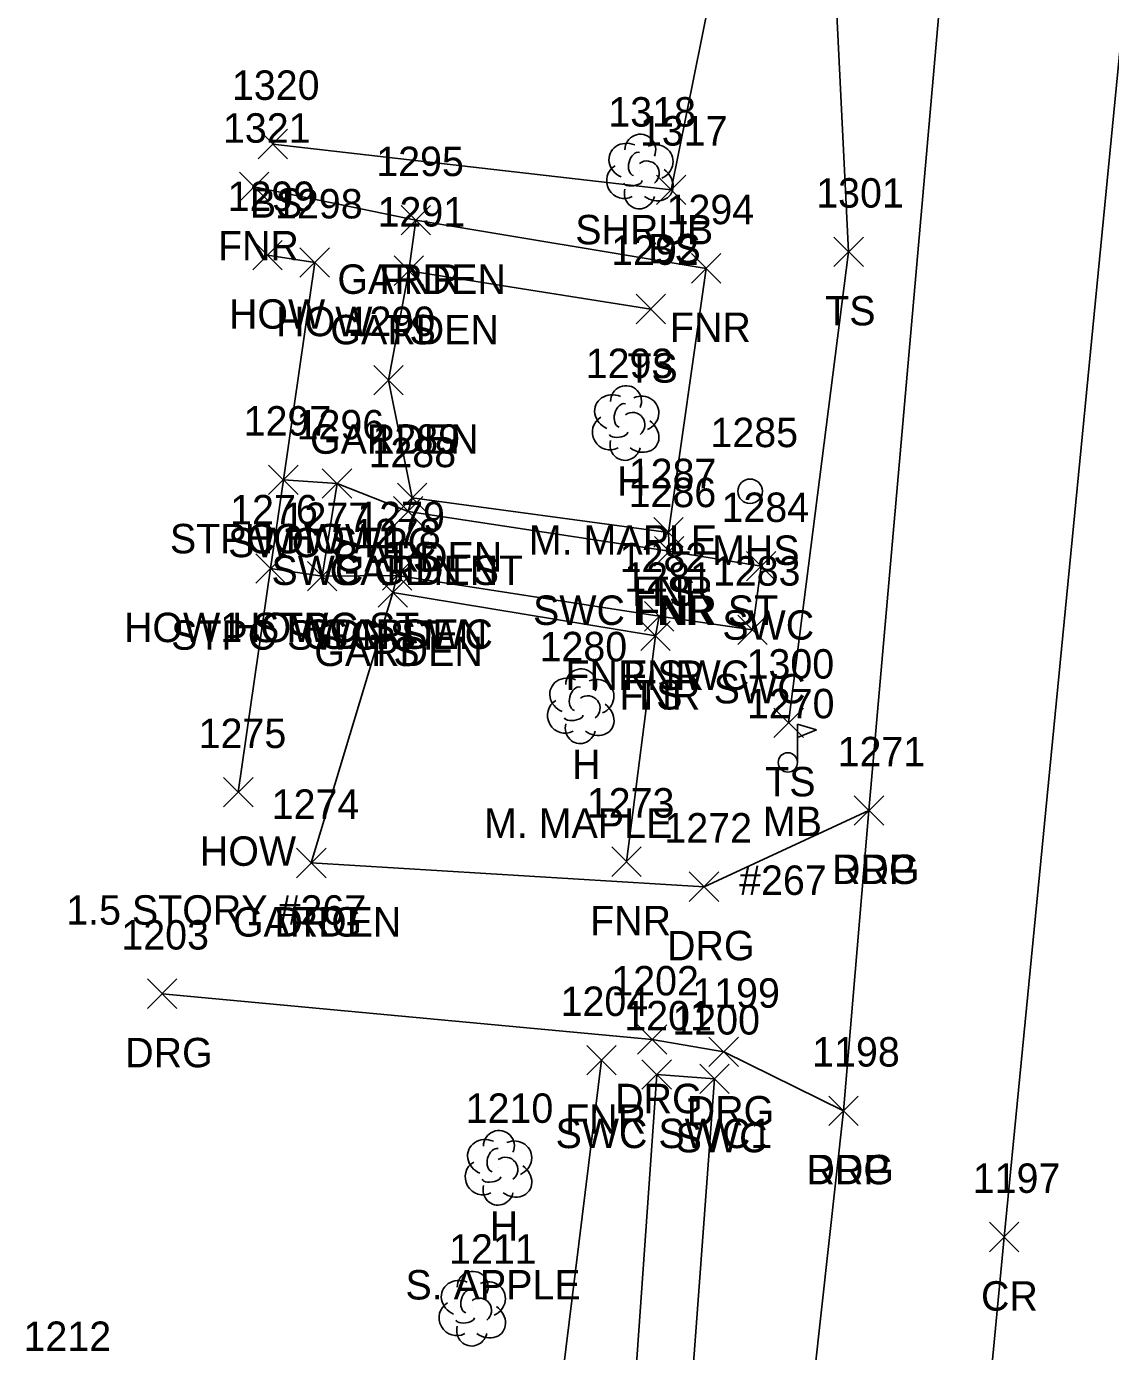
# Model space of a CAD drawing. Extents: x 1653908 to 1654393, y 539913 to 544256.
# Drawn here: x 1653967.4 to 1654041, y 541291.8 to 541381.8 of the extents above; entities that cross this region are included whole.
import ezdxf

# ---------------------------------------------------------------- set-up
doc = ezdxf.new("R2010")
doc.units = 0
for name, color, linetype in [('L_A', 7, 'Continuous'), ('L_C', 7, 'Continuous'), ('L_I', 7, 'Continuous'), ('L_TIC', 7, 'Continuous'), ('LAPB', 7, 'Continuous'), ('LBC', 7, 'Continuous'), ('LBF', 7, 'Continuous'), ('LELB', 7, 'Continuous'), ('LFNC', 7, 'Continuous'), ('LMB', 7, 'Continuous'), ('LSH', 7, 'Continuous'), ('LTD', 7, 'Continuous'), ('P_A', 7, 'Continuous'), ('P_I', 7, 'Continuous'), ('P_TIC', 7, 'Continuous'), ('PET', 7, 'Continuous'), ('PRC', 7, 'Continuous'), ('R_A', 7, 'Continuous'), ('R_I', 7, 'Continuous'), ('R_TIC', 7, 'Continuous'), ('RDG', 7, 'Continuous'), ('RSW', 7, 'Continuous'), ('U_A', 7, 'Continuous'), ('U_I', 7, 'Continuous'), ('USMH', 7, 'Continuous')]:
    doc.layers.add(name, color=color, linetype=linetype)

msp = doc.modelspace()

# ---------------------------------------------------------------- linework, layer by layer
at = {"layer": 'L_TIC'}
for points in [[(1653983.158, 541372.791), (1653985.158, 541374.791)], [(1653985.158, 541372.791), (1653983.158, 541374.791)], [(1653981.896, 541369.882), (1653983.896, 541371.882)], [(1653983.896, 541369.882), (1653981.896, 541371.882)], [(1654010.21, 541369.687), (1654012.21, 541371.687)], [(1654012.21, 541369.687), (1654010.21, 541371.687)], [(1653992.873, 541367.614), (1653994.873, 541369.614)], [(1653994.873, 541367.614), (1653992.873, 541369.614)], [(1653992.873, 541367.614), (1653994.873, 541369.614)], [(1653994.873, 541367.614), (1653992.873, 541369.614)], [(1654022.261, 541365.471), (1654024.261, 541367.471)], [(1654024.261, 541365.471), (1654022.261, 541367.471)], [(1653982.792, 541365.244), (1653984.792, 541367.244)], [(1653984.792, 541365.244), (1653982.792, 541367.244)], [(1653986, 541364.736), (1653988, 541366.736)], [(1653988, 541364.736), (1653986, 541366.736)], [(1653992.398, 541364.185), (1653994.398, 541366.185)], [(1653994.398, 541364.185), (1653992.398, 541366.185)], [(1653992.398, 541364.185), (1653994.398, 541366.185)], [(1653994.398, 541364.185), (1653992.398, 541366.185)], [(1654012.586, 541364.344), (1654014.586, 541366.344)], [(1654014.586, 541364.344), (1654012.586, 541366.344)], [(1654008.827, 541361.582), (1654010.827, 541363.582)], [(1654010.827, 541361.582), (1654008.827, 541363.582)], [(1653991.014, 541356.749), (1653993.014, 541358.749)], [(1653993.014, 541356.749), (1653991.014, 541358.749)], [(1653983.872, 541349.985), (1653985.872, 541351.985)], [(1653985.872, 541349.985), (1653983.872, 541351.985)], [(1653983.872, 541349.985), (1653985.872, 541351.985)], [(1653985.872, 541349.985), (1653983.872, 541351.985)], [(1653987.519, 541349.723), (1653989.519, 541351.723)], [(1653989.519, 541349.723), (1653987.519, 541351.723)], [(1653992.626, 541348.749), (1653994.626, 541350.749)], [(1653994.626, 541348.749), (1653992.626, 541350.749)], [(1653992.626, 541348.749), (1653994.626, 541350.749)], [(1653994.626, 541348.749), (1653992.626, 541350.749)], [(1653992.348, 541347.837), (1653994.348, 541349.837)], [(1653994.348, 541347.837), (1653992.348, 541349.837)], [(1654010.021, 541346.41), (1654012.021, 541348.41)], [(1654012.021, 541346.41), (1654010.021, 541348.41)], [(1654010.021, 541346.41), (1654012.021, 541348.41)], [(1654012.021, 541346.41), (1654010.021, 541348.41)], [(1654010.066, 541345.122), (1654012.066, 541347.122)], [(1654012.066, 541345.122), (1654010.066, 541347.122)], [(1653983.009, 541343.952), (1653985.009, 541345.952)], [(1653985.009, 541343.952), (1653983.009, 541345.952)], [(1653983.009, 541343.952), (1653985.009, 541345.952)], [(1653985.009, 541343.952), (1653983.009, 541345.952)], [(1653986.513, 541343.436), (1653988.513, 541345.436)], [(1653988.513, 541343.436), (1653986.513, 541345.436)], [(1653991.598, 541343.49), (1653993.598, 541345.49)], [(1653993.598, 541343.49), (1653991.598, 541345.49)], [(1653991.302, 541342.326), (1653993.302, 541344.326)], [(1653993.302, 541342.326), (1653991.302, 541344.326)], [(1653991.302, 541342.326), (1653993.302, 541344.326)], [(1653993.302, 541342.326), (1653991.302, 541344.326)], [(1654009.4, 541340.707), (1654011.4, 541342.707)], [(1654011.4, 541340.707), (1654009.4, 541342.707)], [(1654009.15, 541339.375), (1654011.15, 541341.375)], [(1654011.15, 541339.375), (1654009.15, 541341.375)], [(1654009.15, 541339.375), (1654011.15, 541341.375)], [(1654011.15, 541339.375), (1654009.15, 541341.375)], [(1654018.186, 541333.474), (1654020.186, 541335.474)], [(1654020.186, 541333.474), (1654018.186, 541335.474)], [(1653980.815, 541328.756), (1653982.815, 541330.756)], [(1653982.815, 541328.756), (1653980.815, 541330.756)], [(1653985.773, 541323.947), (1653987.773, 541325.947)], [(1653987.773, 541323.947), (1653985.773, 541325.947)], [(1654007.171, 541324.034), (1654009.171, 541326.034)], [(1654009.171, 541324.034), (1654007.171, 541326.034)], [(1654005.471, 541310.553), (1654007.471, 541312.553)], [(1654007.471, 541310.553), (1654005.471, 541312.553)]]:
    msp.add_lwpolyline(points, dxfattribs=at)
at = {"layer": 'LAPB'}
for points in [[(1653993.348, 541348.837), (1653993.626, 541349.749), (1653992.014, 541357.749), (1653993.398, 541365.185), (1653993.873, 541368.614)], [(1653986.773, 541324.947), (1653992.302, 541343.326), (1653992.598, 541344.49)]]:
    msp.add_lwpolyline(points, dxfattribs=at)
at = {"layer": 'LBC'}
msp.add_lwpolyline([(1653981.815, 541329.756), (1653984.009, 541344.952), (1653984.872, 541350.985), (1653987, 541365.736), (1653983.792, 541366.244)], dxfattribs=at)
at = {"layer": 'LBF'}
msp.add_lwpolyline([(1653984.009, 541344.952), (1653987.513, 541344.436), (1653988.519, 541350.723), (1653984.872, 541350.985)], dxfattribs=at)
at = {"layer": 'LELB'}
for points in [[(1654019.186, 541334.474), (1654023.261, 541366.471), (1654022.174, 541388.621), (1654024.472, 541409.633), (1654022.609, 541414.814), (1654017.025, 541416.388), (1653986.915, 541424.555)], [(1653986.851, 541419.767), (1654010.112, 541412.292), (1654017.524, 541409.875), (1654019.555, 541413.789), (1654020.683, 541413.911), (1654020.292, 541406.568), (1654014.863, 541388.785), (1654011.21, 541370.687), (1653984.158, 541373.791)], [(1653993.398, 541365.185), (1654009.827, 541362.582)], [(1654011.021, 541347.41), (1653993.626, 541349.749)], [(1653992.302, 541343.326), (1654010.15, 541340.375)]]:
    msp.add_lwpolyline(points, dxfattribs=at)
at = {"layer": 'LFNC'}
for points in [[(1654011.066, 541346.122), (1654011.021, 541347.41), (1654013.586, 541365.344), (1653993.873, 541368.614), (1653982.896, 541370.882)], [(1654008.171, 541325.034), (1654010.15, 541340.375), (1654010.4, 541341.707)], [(1654006.471, 541311.553), (1654003.182, 541284.757), (1653969.354, 541288.797)]]:
    msp.add_lwpolyline(points, dxfattribs=at)
at = {"layer": 'LMB'}
for p, q in [((1654019.779, 541334.379), (1654021.073, 541333.997)), ((1654019.786, 541331.787), (1654019.784, 541334.381)), ((1654019.784, 541333.48), (1654021.067, 541333.988)), ((1654019.13, 541331.778), (1654019.13, 541331.778))]:
    msp.add_line(p, q, dxfattribs=at)
msp.add_circle((1654019.129, 541331.778), 0.656, dxfattribs=at)
at = {"layer": 'LSH'}
msp.add_line((1654009.067, 541371.976), (1654009.067, 541371.976), dxfattribs=at)
msp.add_line((1654009.067, 541371.976), (1654009.067, 541371.976), dxfattribs=at)
msp.add_arc((1654009.114, 541373.41), 1.047, 335.52715, 180.95627, dxfattribs=at)
for centre, major_axis, ratio, start_param, end_param in [((1654008.275, 541372.643), (1.21, -0.512), 0.895232, 1.570796, 4.712389), ((1654010.109, 541372.56), (-1.141, -0.483), 0.949671, 1.570796, 4.712389), ((1654008.859, 541372.435), (-0.208, -0.792), 0.645439, 3.141593, 6.283185), ((1654009.567, 541371.81), (-0.5, 0.667), 0.989748, 3.141593, 6.283185), ((1654007.984, 541371.268), (0.584, -1.042), 0.959034, 3.141593, 6.283185), ((1654010.067, 541371.143), (-1.09, 0.792), 0.841452, 1.570796, 4.712389), ((1654008.609, 541371.226), (-0.625, -0.083), 0.423636, 0, 3.141593), ((1654009.067, 541370.476), (0.265, 1.061), 0.942809, 1.570796, 4.712389)]:
    msp.add_ellipse(centre, major_axis=major_axis, ratio=ratio, start_param=start_param, end_param=end_param, dxfattribs=at)
at = {"layer": 'LTD'}
for p, q in [((1654008.098, 541354.892), (1654008.098, 541354.892)), ((1654008.098, 541354.892), (1654008.098, 541354.892)), ((1654005.051, 541335.651), (1654005.051, 541335.651)), ((1654005.051, 541335.651), (1654005.051, 541335.651)), ((1653999.466, 541304.293), (1653999.466, 541304.293)), ((1653999.466, 541304.293), (1653999.466, 541304.293)), ((1653997.685, 541294.723), (1653997.685, 541294.723)), ((1653997.685, 541294.723), (1653997.685, 541294.723))]:
    msp.add_line(p, q, dxfattribs=at)
for centre in [(1654008.145, 541356.326), (1654005.097, 541337.085), (1653999.513, 541305.727), (1653997.732, 541296.157)]:
    msp.add_arc(centre, 1.047, 335.52715, 180.95627, dxfattribs=at)
for centre, major_axis, ratio, start_param, end_param in [((1654007.306, 541355.559), (1.21, -0.512), 0.895232, 1.570796, 4.712389), ((1654009.14, 541355.476), (-1.141, -0.483), 0.949671, 1.570796, 4.712389), ((1654007.89, 541355.351), (-0.208, -0.792), 0.645439, 3.141593, 6.283185), ((1654008.598, 541354.726), (-0.5, 0.667), 0.989748, 3.141593, 6.283185), ((1654007.015, 541354.184), (0.584, -1.042), 0.959034, 3.141593, 6.283185), ((1654009.098, 541354.059), (-1.09, 0.792), 0.841452, 1.570796, 4.712389), ((1654007.64, 541354.142), (-0.625, -0.083), 0.423636, 0, 3.141593), ((1654008.098, 541353.392), (0.265, 1.061), 0.942809, 1.570796, 4.712389), ((1654004.259, 541336.318), (1.21, -0.512), 0.895232, 1.570796, 4.712389), ((1654006.092, 541336.235), (-1.141, -0.483), 0.949671, 1.570796, 4.712389), ((1654004.842, 541336.11), (-0.208, -0.792), 0.645439, 3.141593, 6.283185), ((1654003.967, 541334.943), (0.584, -1.042), 0.959034, 3.141593, 6.283185), ((1654005.551, 541335.485), (-0.5, 0.667), 0.989748, 3.141593, 6.283185), ((1654004.592, 541334.901), (-0.625, -0.083), 0.423636, 0, 3.141593), ((1654006.051, 541334.818), (-1.09, 0.792), 0.841452, 1.570796, 4.712389), ((1654005.051, 541334.151), (0.265, 1.061), 0.942809, 1.570796, 4.712389), ((1653998.674, 541304.96), (1.21, -0.512), 0.895232, 1.570796, 4.712389), ((1654000.508, 541304.877), (-1.141, -0.483), 0.949671, 1.570796, 4.712389), ((1653999.258, 541304.752), (-0.208, -0.792), 0.645439, 3.141593, 6.283185), ((1653998.383, 541303.585), (0.584, -1.042), 0.959034, 3.141593, 6.283185), ((1653999.966, 541304.127), (-0.5, 0.667), 0.989748, 3.141593, 6.283185), ((1654000.466, 541303.46), (-1.09, 0.792), 0.841452, 1.570796, 4.712389), ((1653999.008, 541303.543), (-0.625, -0.083), 0.423636, 0, 3.141593), ((1653999.466, 541302.793), (0.265, 1.061), 0.942809, 1.570796, 4.712389), ((1653996.893, 541295.39), (1.21, -0.512), 0.895232, 1.570796, 4.712389), ((1653998.726, 541295.307), (-1.141, -0.483), 0.949671, 1.570796, 4.712389), ((1653997.476, 541295.181), (-0.208, -0.792), 0.645439, 3.141593, 6.283185), ((1653998.185, 541294.556), (-0.5, 0.667), 0.989748, 3.141593, 6.283185), ((1653996.602, 541294.014), (0.584, -1.042), 0.959034, 3.141593, 6.283185), ((1653998.685, 541293.89), (-1.09, 0.792), 0.841452, 1.570796, 4.712389), ((1653997.685, 541293.223), (0.265, 1.061), 0.942809, 1.570796, 4.712389), ((1653997.227, 541293.973), (-0.625, -0.083), 0.423636, 0, 3.141593)]:
    msp.add_ellipse(centre, major_axis=major_axis, ratio=ratio, start_param=start_param, end_param=end_param, dxfattribs=at)
at = {"layer": 'P_TIC'}
for points in [[(1654023.639, 541327.517), (1654025.639, 541329.517)], [(1654025.639, 541327.517), (1654023.639, 541329.517)], [(1654021.907, 541307.117), (1654023.907, 541309.117)], [(1654023.907, 541307.117), (1654021.907, 541309.117)], [(1654032.814, 541298.535), (1654034.814, 541300.535)], [(1654034.814, 541298.535), (1654032.814, 541300.535)]]:
    msp.add_lwpolyline(points, dxfattribs=at)
at = {"layer": 'PET'}
msp.add_lwpolyline([(1654002.711, 541022.85), (1654002.8, 541044.575), (1654003.387, 541071.89), (1654004.237, 541078.688), (1654006.743, 541130.143), (1654008.352, 541153.982), (1654010.069, 541183.44), (1654012.885, 541209.942), (1654016.448, 541249.52), (1654022.907, 541308.117), (1654024.639, 541328.517), (1654031.788, 541410.001), (1654035.81, 541442.822), (1654037.011, 541460.368), (1654040.035, 541491.488), (1654045.583, 541525.885), (1654049.594, 541568.112), (1654053.328, 541590.161), (1654054.271, 541598.349), (1654062.589, 541587.523), (1654071.875, 541577.056), (1654070.193, 541559.907), (1654067.659, 541531.505), (1654064.32, 541497.282)], dxfattribs=at)
at = {"layer": 'PRC'}
msp.add_lwpolyline([(1654015.219, 541022.422), (1654016.681, 541078.091), (1654019.776, 541129.034), (1654023.084, 541180.037), (1654025.544, 541208.787), (1654028.973, 541248.663), (1654033.814, 541299.535), (1654044.549, 541409.641), (1654048.398, 541449.608), (1654049.075, 541458.744), (1654052.537, 541493.395), (1654055.938, 541523.167), (1654060.179, 541564.47), (1654062.589, 541587.523)], dxfattribs=at)
at = {"layer": 'R_TIC'}
for points in [[(1653987.519, 541349.723), (1653989.519, 541351.723)], [(1653989.519, 541349.723), (1653987.519, 541351.723)], [(1653992.348, 541347.837), (1653994.348, 541349.837)], [(1653994.348, 541347.837), (1653992.348, 541349.837)], [(1654010.066, 541345.122), (1654012.066, 541347.122)], [(1654012.066, 541345.122), (1654010.066, 541347.122)], [(1654016.32, 541344.115), (1654018.32, 541346.115)], [(1654018.32, 541344.115), (1654016.32, 541346.115)], [(1653986.513, 541343.436), (1653988.513, 541345.436)], [(1653988.513, 541343.436), (1653986.513, 541345.436)], [(1653991.598, 541343.49), (1653993.598, 541345.49)], [(1653993.598, 541343.49), (1653991.598, 541345.49)], [(1654009.4, 541340.707), (1654011.4, 541342.707)], [(1654011.4, 541340.707), (1654009.4, 541342.707)], [(1654015.734, 541339.79), (1654017.734, 541341.79)], [(1654017.734, 541339.79), (1654015.734, 541341.79)], [(1654023.639, 541327.517), (1654025.639, 541329.517)], [(1654025.639, 541327.517), (1654023.639, 541329.517)], [(1653985.773, 541323.947), (1653987.773, 541325.947)], [(1653987.773, 541323.947), (1653985.773, 541325.947)], [(1654012.44, 541322.338), (1654014.44, 541324.338)], [(1654014.44, 541322.338), (1654012.44, 541324.338)], [(1653975.644, 541315.067), (1653977.644, 541317.067)], [(1653977.644, 541315.067), (1653975.644, 541317.067)], [(1654008.914, 541311.951), (1654010.914, 541313.951)], [(1654010.914, 541311.951), (1654008.914, 541313.951)], [(1654013.775, 541311.114), (1654015.775, 541313.114)], [(1654015.775, 541311.114), (1654013.775, 541313.114)], [(1654009.225, 541309.577), (1654011.225, 541311.577)], [(1654011.225, 541309.577), (1654009.225, 541311.577)], [(1654009.225, 541309.577), (1654011.225, 541311.577)], [(1654011.225, 541309.577), (1654009.225, 541311.577)], [(1654013.15, 541309.291), (1654015.15, 541311.291)], [(1654015.15, 541309.291), (1654013.15, 541311.291)], [(1654021.907, 541307.117), (1654023.907, 541309.117)], [(1654023.907, 541307.117), (1654021.907, 541309.117)]]:
    msp.add_lwpolyline(points, dxfattribs=at)
at = {"layer": 'RDG'}
for points in [[(1654024.639, 541328.517), (1654013.44, 541323.338), (1653986.773, 541324.947)], [(1654022.907, 541308.117), (1654014.775, 541312.114), (1654009.914, 541312.951), (1653976.644, 541316.067)]]:
    msp.add_lwpolyline(points, dxfattribs=at)
at = {"layer": 'RSW'}
for points in [[(1653987.513, 541344.436), (1653992.598, 541344.49), (1654010.4, 541341.707), (1654016.734, 541340.79), (1654017.32, 541345.115), (1654011.066, 541346.122), (1653993.348, 541348.837), (1653988.519, 541350.723)], [(1653995.608, 541066.356), (1653991.562, 541066.058), (1653992.581, 541078.58), (1653996.533, 541130.668), (1653999, 541158.35), (1654000.182, 541180.988), (1654002.98, 541210.258), (1654005.98, 541249.997), (1654010.225, 541310.577)], [(1653995.608, 541066.356), (1653996.516, 541078.59), (1654000.449, 541130.29), (1654004.364, 541181.55), (1654006.659, 541209.967), (1654009.695, 541249.872), (1654014.15, 541310.291), (1654010.225, 541310.577)]]:
    msp.add_lwpolyline(points, dxfattribs=at)
at = {"layer": 'USMH'}
for p, q in [((1654016.568, 541350.198), (1654016.568, 541350.198)), ((1654017.402, 541350.198), (1654017.402, 541350.198))]:
    msp.add_line(p, q, dxfattribs=at)
msp.add_circle((1654016.568, 541350.198), 0.833, dxfattribs=at)

# ---------------------------------------------------------------- texts
at = {"layer": 'L_A'}
for s, p in [('BS', (1653982.599, 541368.791)), ('SHRUB', (1654004.697, 541366.976)), ('FNR', (1653980.431, 541365.882)), ('BS', (1654009.651, 541365.687)), ('GARDEN', (1653988.543, 541363.614)), ('FNR', (1653991.409, 541363.614)), ('HOW', (1653981.178, 541361.244)), ('TS', (1654021.67, 541361.471)), ('HOW', (1653984.386, 541360.736)), ('GARDEN', (1653988.067, 541360.185)), ('TS', (1653991.807, 541360.185)), ('FNR', (1654011.122, 541360.344)), ('TS', (1654008.236, 541357.582)), ('GARDEN', (1653986.683, 541352.749)), ('H', (1654007.531, 541349.892)), ('STPC HOW1', (1653977.171, 541345.985)), ('SWC STPC', (1653981.126, 541345.723)), ('HOW', (1653982.258, 541345.985)), ('GARDEN', (1653988.295, 541344.749)), ('TS', (1653992.036, 541344.749)), ('GARDEN', (1653988.018, 541343.837)), ('FNR', (1654008.557, 541342.41)), ('TS', (1654009.431, 541342.41)), ('FNR', (1654008.601, 541341.122)), ('HOW1 STPC ST', (1653974.049, 541339.952)), ('STPC SWC ST', (1653977.253, 541339.436)), ('HOW', (1653981.395, 541339.952)), ('GARDEN', (1653987.267, 541339.49)), ('GARDEN', (1653986.971, 541338.326)), ('TS', (1653990.711, 541338.326)), ('FNR', (1654007.935, 541336.707)), ('FNR', (1654007.685, 541335.375)), ('TS', (1654008.559, 541335.375)), ('H', (1654004.484, 541330.651)), ('TS', (1654017.596, 541329.474)), ('MB', (1654017.437, 541326.778)), ('HOW', (1653979.201, 541324.756)), ('GARDEN', (1653981.443, 541319.947)), ('FNR', (1654005.706, 541320.034)), ('FNR', (1654004.006, 541306.553)), ('H', (1653998.899, 541299.293))]:
    msp.add_text(s, height=2, dxfattribs=at).set_placement(p)
at = {"layer": 'L_C'}
for s, p in [('M. MAPLE', (1654001.547, 541345.892)), ('M. MAPLE', (1653998.5, 541326.651)), ('#267', (1654015.822, 541322.778)), ('1.5 STORY #267', (1653970.13, 541320.756)), ('S. APPLE', (1653993.167, 541295.293))]:
    msp.add_text(s, height=2, dxfattribs=at).set_placement(p)
at = {"layer": 'L_I'}
for s, p in [('1320', (1653981.379, 541376.791)), ('1318', (1654006.941, 541374.976)), ('1321', (1653980.77, 541373.882)), ('1317', (1654009.084, 541373.687)), ('1295', (1653991.181, 541371.614)), ('1295', (1653991.181, 541371.614)), ('1299', (1653981.091, 541369.244)), ('1301', (1654021.056, 541369.471)), ('1298', (1653984.308, 541368.736)), ('1291', (1653991.272, 541368.185)), ('1291', (1653991.272, 541368.185)), ('1294', (1654010.894, 541368.344)), ('1292', (1654007.134, 541365.582)), ('1290', (1653989.235, 541360.749)), ('1293', (1654005.406, 541357.892)), ('1297', (1653982.179, 541353.985)), ('1297', (1653982.179, 541353.985)), ('1296', (1653985.771, 541353.723)), ('1289', (1653990.926, 541352.749)), ('1289', (1653990.926, 541352.749)), ('1288', (1653990.656, 541351.837)), ('1287', (1654008.328, 541350.41)), ('1287', (1654008.328, 541350.41)), ('1286', (1654008.318, 541349.122)), ('1276', (1653981.261, 541347.952)), ('1276', (1653981.261, 541347.952)), ('1277', (1653984.82, 541347.436)), ('1279', (1653989.897, 541347.49)), ('1278', (1653989.609, 541346.326)), ('1278', (1653989.609, 541346.326)), ('1282', (1654007.707, 541344.707)), ('1281', (1654008.024, 541343.375)), ('1281', (1654008.024, 541343.375)), ('1280', (1654002.271, 541338.651)), ('1300', (1654016.328, 541337.474)), ('1270', (1654016.35, 541334.778)), ('1275', (1653979.122, 541332.756)), ('1274', (1653984.081, 541327.947)), ('1273', (1654005.478, 541328.034)), ('1204', (1654003.699, 541314.553)), ('1210', (1653997.254, 541307.293)), ('1211', (1653996.126, 541297.723)), ('1212', (1653967.228, 541291.797))]:
    msp.add_text(s, height=2, dxfattribs=at).set_placement(p)
at = {"layer": 'P_A'}
for s, p in [('RDP', (1654022.127, 541323.517)), ('RDP', (1654020.395, 541303.117)), ('CR', (1654032.248, 541294.535))]:
    msp.add_text(s, height=2, dxfattribs=at).set_placement(p)
at = {"layer": 'P_I'}
for s, p in [('1271', (1654022.513, 541331.517)), ('1198', (1654020.782, 541311.117)), ('1197', (1654031.689, 541302.535))]:
    msp.add_text(s, height=2, dxfattribs=at).set_placement(p)
at = {"layer": 'R_A'}
for s, p in [('SWC STPC', (1653981.126, 541345.723)), ('SWC GDN ST', (1653984.065, 541343.837)), ('SWC FNR ST', (1654001.83, 541341.122)), ('SWC', (1654014.682, 541340.115)), ('STPC SWC ST', (1653977.253, 541339.436)), ('GDN SWC', (1653986.181, 541339.49)), ('FNR SWC', (1654004.03, 541336.707)), ('SWC', (1654014.096, 541335.79)), ('DRG', (1654022.127, 541323.517)), ('DRG', (1653984.262, 541319.947)), ('DRG', (1654010.928, 541318.338)), ('DRG', (1653974.132, 541311.067)), ('DRG', (1654007.403, 541307.951)), ('DRG', (1654012.263, 541307.114)), ('SWC SWC1', (1654003.359, 541305.577)), ('SWC SWC1', (1654003.359, 541305.577)), ('SWC', (1654011.512, 541305.291)), ('DRG', (1654020.395, 541303.117))]:
    msp.add_text(s, height=2, dxfattribs=at).set_placement(p)
at = {"layer": 'R_I'}
for s, p in [('1296', (1653985.771, 541353.723)), ('1288', (1653990.656, 541351.837)), ('1286', (1654008.318, 541349.122)), ('1277', (1653984.82, 541347.436)), ('1279', (1653989.897, 541347.49)), ('1284', (1654014.627, 541348.115)), ('1282', (1654007.707, 541344.707)), ('1283', (1654014.041, 541343.79)), ('1271', (1654022.513, 541331.517)), ('1274', (1653984.081, 541327.947)), ('1272', (1654010.748, 541326.338)), ('1203', (1653973.873, 541319.067)), ('1202', (1654007.143, 541315.951)), ('1199', (1654012.642, 541315.114)), ('1201', (1654008.021, 541313.577)), ('1201', (1654008.021, 541313.577)), ('1200', (1654011.292, 541313.291)), ('1198', (1654020.782, 541311.117))]:
    msp.add_text(s, height=2, dxfattribs=at).set_placement(p)
at = {"layer": 'U_A'}
msp.add_text('MHS', height=2, dxfattribs=at).set_placement((1654013.986, 541345.198))
at = {"layer": 'U_I'}
msp.add_text('1285', height=2, dxfattribs=at).set_placement((1654013.875, 541353.198))

doc.saveas('drawing.dxf')
